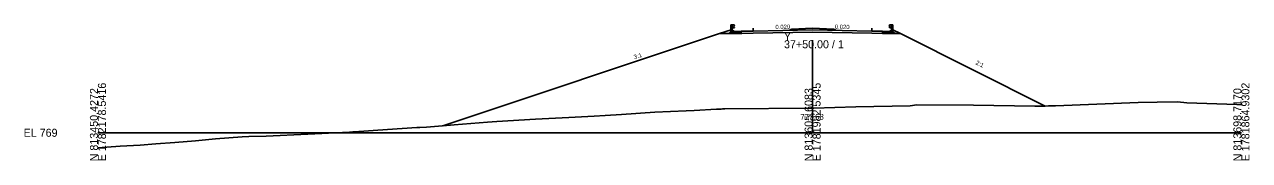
# Model space of a CAD drawing. Extents: x -12583 to 5303, y -44 to 25667.
# Drawn here: x 1874.3 to 2302.8, y 7990.3 to 8037.8 of the extents above; entities that cross this region are included whole.
import ezdxf

# ---------------------------------------------------------------- set-up
doc = ezdxf.new("R2010")
doc.units = 0
for name, color, linetype in [('Exist Cross Section Cell', 7, 'Continuous'), ('Exist XS Center Line Elevation Label', 7, 'Continuous'), ('Exist XS Ground Line', 7, 'Continuous'), ('Prop Conc 5in Monolithic Surface Mount Island', 7, 'Continuous'), ('Prop XS Dump Level', 7, 'Continuous'), ('Prop XS Earthwork Shape', 7, 'Continuous'), ('Prop XS EOT Tick Mark', 7, 'Continuous'), ('Prop XS Finish Grade', 7, 'Continuous'), ('Prop XS Finish Grade CurbGutter', 7, 'Continuous'), ('Prop XS Finish Grade Earthwork', 7, 'Continuous'), ('Prop XS Finish Grade Paved Shoulder', 7, 'Continuous'), ('Prop XS Finish Grade Pavement', 7, 'Continuous'), ('Prop XS Guardrail', 7, 'Continuous'), ('Prop XS Pvmt Edge Slope', 7, 'Continuous'), ('Prop XS SE Text', 7, 'Continuous'), ('Prop XS Side Slope Text', 7, 'Continuous'), ('Prop XS Subgrade CurbGutter', 7, 'Continuous'), ('Prop XS Subgrade Earthwork', 7, 'Continuous')]:
    doc.layers.add(name, color=color, linetype=linetype)

msp = doc.modelspace()

# ---------------------------------------------------------------- linework, layer by layer
at = {"layer": 'Exist Cross Section Cell'}
for p, q in [((2150, 8000), (2150, 8032.33)), ((1900, 8000), (2150, 8000)), ((2150, 8000), (2300, 8000))]:
    msp.add_line(p, q, dxfattribs=at)
at = {"layer": 'Exist XS Ground Line'}
for p, q in [((2165.07, 8009.08), (2184.12, 8009.45)), ((2184.12, 8009.45), (2186.46, 8009.8)), ((2186.46, 8009.8), (2206.34, 8009.67)), ((2206.34, 8009.67), (2227.74, 8009.34)), ((2227.74, 8009.34), (2232.53, 8009.36)), ((2232.53, 8009.36), (2234.96, 8009.41)), ((2234.96, 8009.41), (2263.89, 8010.55)), ((2263.89, 8010.55), (2270.59, 8010.68)), ((2270.59, 8010.68), (2277.64, 8010.78)), ((2277.64, 8010.78), (2280.86, 8010.51)), ((2280.86, 8010.51), (2298.39, 8009.82)), ((2298.39, 8009.82), (2300, 8009.72)), ((2053.04, 8004.8), (2064.78, 8005.35)), ((2064.78, 8005.35), (2073.57, 8005.79)), ((2073.57, 8005.79), (2077.49, 8006.04)), ((2077.49, 8006.04), (2083.14, 8006.35)), ((2083.14, 8006.35), (2094.81, 8007.14)), ((2094.81, 8007.14), (2105.81, 8007.69)), ((2105.81, 8007.69), (2108.53, 8007.77)), ((2108.53, 8007.77), (2116.37, 8008.23)), ((2116.37, 8008.23), (2117.98, 8008.3)), ((2117.98, 8008.3), (2118.47, 8008.32)), ((2118.47, 8008.32), (2119.35, 8008.35)), ((2119.35, 8008.35), (2150, 8008.58)), ((2150, 8008.58), (2150.4, 8008.58)), ((2150.4, 8008.58), (2165.07, 8009.08)), ((1989.62, 8000.34), (2001.3, 8001.14)), ((2001.3, 8001.14), (2011.53, 8001.78)), ((2011.53, 8001.78), (2012.66, 8001.88)), ((2012.66, 8001.88), (2014.91, 8001.98)), ((2014.91, 8001.98), (2024.63, 8002.71)), ((2024.63, 8002.71), (2036.26, 8003.66)), ((2036.26, 8003.66), (2039.49, 8003.94)), ((2039.49, 8003.94), (2053.04, 8004.8)), ((1920.29, 7996.12), (1926.85, 7996.62)), ((1926.85, 7996.62), (1934.12, 7997.19)), ((1934.12, 7997.19), (1941.08, 7997.87)), ((1941.08, 7997.87), (1950.51, 7998.6)), ((1950.51, 7998.6), (1952.83, 7998.74)), ((1952.83, 7998.74), (1958.88, 7998.84)), ((1958.88, 7998.84), (1987.99, 8000.26)), ((1987.99, 8000.26), (1989.18, 8000.32)), ((1989.18, 8000.32), (1989.62, 8000.34)), ((1900, 7994.73), (1907.79, 7995.26)), ((1907.79, 7995.26), (1914.74, 7995.7)), ((1914.74, 7995.7), (1920.29, 7996.12))]:
    msp.add_line(p, q, dxfattribs=at)
at = {"layer": 'Prop Conc 5in Monolithic Surface Mount Island'}
for p, q in [((2142, 8035.98), (2142.74, 8036.24)), ((2142, 8035.81), (2142, 8035.98)), ((2142.74, 8036.24), (2150, 8036.53)), ((2157.26, 8036.24), (2150, 8036.53)), ((2158, 8035.98), (2157.26, 8036.24)), ((2158, 8035.81), (2158, 8035.98))]:
    msp.add_line(p, q, dxfattribs=at)
at = {"layer": 'Prop XS Dump Level'}
for p, q in [((2129.25, 8035.56), (2150, 8035.97)), ((2150, 8035.97), (2170.75, 8035.56))]:
    msp.add_line(p, q, dxfattribs=at)
at = {"layer": 'Prop XS Earthwork Shape'}
msp.add_lwpolyline([(2125.25, 8034.68), (2125.06, 8034.68), (2120.67, 8034.68), (2117.46, 8034.68), (2020.66, 8002.41), (2024.63, 8002.71), (2036.26, 8003.66), (2039.49, 8003.94), (2053.04, 8004.8), (2064.78, 8005.35), (2073.57, 8005.79), (2077.49, 8006.04), (2083.14, 8006.35), (2094.81, 8007.14), (2105.81, 8007.69), (2108.53, 8007.77), (2116.37, 8008.23), (2117.98, 8008.3), (2118.47, 8008.32), (2119.35, 8008.35), (2150, 8008.58), (2150.4, 8008.58), (2165.07, 8009.08), (2184.12, 8009.45), (2186.46, 8009.8), (2206.34, 8009.67), (2227.74, 8009.34), (2231.38, 8009.35), (2180.72, 8034.69), (2178.84, 8034.69), (2174.45, 8034.69), (2170.75, 8034.76), (2150, 8035.18), (2129.25, 8034.76)], close=True, dxfattribs=at)
at = {"layer": 'Prop XS EOT Tick Mark'}
for p, q in [((2129.25, 8035.56), (2129.25, 8036.56)), ((2170.75, 8035.56), (2170.75, 8036.56))]:
    msp.add_line(p, q, dxfattribs=at)
at = {"layer": 'Prop XS Finish Grade'}
for p, q in [((2121.46, 8036.01), (2117.46, 8034.68)), ((2122.04, 8035.72), (2121.46, 8036.01)), ((2177.47, 8035.73), (2178.05, 8036.02)), ((2180.72, 8034.69), (2178.05, 8036.02))]:
    msp.add_line(p, q, dxfattribs=at)
at = {"layer": 'Prop XS Finish Grade CurbGutter'}
for p, q in [((2122.73, 8035.38), (2122.04, 8035.72)), ((2125.06, 8035.47), (2122.73, 8035.38)), ((2174.45, 8035.48), (2176.78, 8035.39)), ((2176.78, 8035.39), (2177.47, 8035.73))]:
    msp.add_line(p, q, dxfattribs=at)
at = {"layer": 'Prop XS Finish Grade Earthwork'}
for p, q in [((2117.46, 8034.68), (2020.66, 8002.41)), ((2180.72, 8034.69), (2231.38, 8009.35))]:
    msp.add_line(p, q, dxfattribs=at)
at = {"layer": 'Prop XS Finish Grade Paved Shoulder'}
for p, q in [((2129.25, 8035.56), (2125.06, 8035.47)), ((2170.75, 8035.56), (2174.45, 8035.48))]:
    msp.add_line(p, q, dxfattribs=at)
at = {"layer": 'Prop XS Finish Grade Pavement'}
for p, q in [((2129.25, 8035.56), (2150, 8035.97)), ((2150, 8035.97), (2170.75, 8035.56))]:
    msp.add_line(p, q, dxfattribs=at)
at = {"layer": 'Prop XS Guardrail'}
for p, q in [((2121.41, 8037.77), (2121.91, 8037.77)), ((2121.41, 8035.27), (2121.41, 8037.77)), ((2121.91, 8037.77), (2122.41, 8037.77)), ((2121.91, 8037.77), (2121.91, 8035.27)), ((2122.41, 8036.64), (2121.91, 8036.64)), ((2122.41, 8037.77), (2122.7, 8037.57)), ((2122.7, 8037.45), (2122.41, 8037.25)), ((2122.41, 8037.25), (2122.41, 8037.16)), ((2122.41, 8037.16), (2122.7, 8036.96)), ((2122.7, 8036.84), (2122.41, 8036.64)), ((2122.7, 8037.57), (2122.73, 8037.51)), ((2122.73, 8037.51), (2122.7, 8037.45)), ((2122.7, 8036.96), (2122.73, 8036.9)), ((2122.73, 8036.9), (2122.7, 8036.84)), ((2176.81, 8037.58), (2176.78, 8037.52)), ((2176.78, 8037.52), (2176.81, 8037.46)), ((2176.81, 8036.97), (2176.78, 8036.91)), ((2176.78, 8036.91), (2176.81, 8036.85)), ((2177.1, 8037.78), (2176.81, 8037.58)), ((2176.81, 8037.46), (2177.1, 8037.26)), ((2177.1, 8037.17), (2176.81, 8036.97)), ((2176.81, 8036.85), (2177.1, 8036.65)), ((2177.6, 8037.78), (2177.1, 8037.78)), ((2177.1, 8037.26), (2177.1, 8037.17)), ((2177.1, 8036.65), (2177.6, 8036.65)), ((2178.1, 8037.78), (2177.6, 8037.78)), ((2177.6, 8037.78), (2177.6, 8035.28)), ((2178.1, 8035.28), (2178.1, 8037.78))]:
    msp.add_line(p, q, dxfattribs=at)
at = {"layer": 'Prop XS Pvmt Edge Slope'}
for p, q in [((2121.04, 8035.05), (2120.67, 8034.68)), ((2122.04, 8035.05), (2121.04, 8035.05)), ((2177.47, 8035.06), (2178.47, 8035.06)), ((2178.47, 8035.06), (2178.84, 8034.69))]:
    msp.add_line(p, q, dxfattribs=at)
at = {"layer": 'Prop XS Subgrade CurbGutter'}
for p, q in [((2122.04, 8035.05), (2122.04, 8035.72)), ((2125.06, 8035.05), (2122.04, 8035.05)), ((2125.06, 8035.47), (2125.06, 8035.05)), ((2174.45, 8035.48), (2174.45, 8035.06)), ((2174.45, 8035.06), (2177.47, 8035.06)), ((2177.47, 8035.06), (2177.47, 8035.73))]:
    msp.add_line(p, q, dxfattribs=at)
at = {"layer": 'Prop XS Subgrade Earthwork'}
for p, q in [((2150, 8035.18), (2129.25, 8034.76)), ((2170.75, 8034.76), (2150, 8035.18)), ((2120.67, 8034.68), (2117.46, 8034.68)), ((2125.06, 8034.68), (2120.67, 8034.68)), ((2125.25, 8034.68), (2125.06, 8034.68)), ((2129.25, 8034.76), (2125.25, 8034.68)), ((2170.75, 8034.76), (2174.45, 8034.69)), ((2174.45, 8034.69), (2178.84, 8034.69)), ((2178.84, 8034.69), (2180.72, 8034.69))]:
    msp.add_line(p, q, dxfattribs=at)

# ---------------------------------------------------------------- texts
at = {"layer": 'Exist Cross Section Cell'}
for s, p in [('Y', (2140, 8032.33)), ('37+50.00 / 1', (2140, 8029.53)), ('EL 769', (1874, 7998.6))]:
    msp.add_text(s, height=2.8, dxfattribs=at).set_placement(p)
for s, p in [('N 813450.4272', (1900, 7990)), ('E 1782178.5416', (1902.8, 7990)), ('N 813605.6083', (2150, 7990)), ('E 1781982.5345', (2152.8, 7990)), ('N 813698.7170', (2300, 7990)), ('E 1781864.9302', (2302.8, 7990))]:
    msp.add_text(s, height=2.8, rotation=90, dxfattribs=at).set_placement(p)
at = {"layer": 'Exist XS Center Line Elevation Label'}
msp.add_text('777.58', height=2, dxfattribs=at).set_placement((2145.73, 8004.58))
at = {"layer": 'Prop XS Dump Level'}
msp.add_text('Case2', height=0.04, dxfattribs=at).set_placement((2174.45, 8035.44))
at = {"layer": 'Prop XS SE Text'}
for rotation, p in [(1.1458, (2137, 8036.21)), (358.8542, (2157.75, 8036.32))]:
    msp.add_text('0.020', height=1.5, rotation=rotation, dxfattribs=at).set_placement(p)
at = {"layer": 'Prop XS Side Slope Text'}
for s, rotation, p in [('3:1', 16.778, (2087.68, 8025.71)), ('2:1', 333.4349, (2206.89, 8024.02))]:
    msp.add_text(s, height=1.5, rotation=rotation, dxfattribs=at).set_placement(p)

doc.saveas('drawing.dxf')
